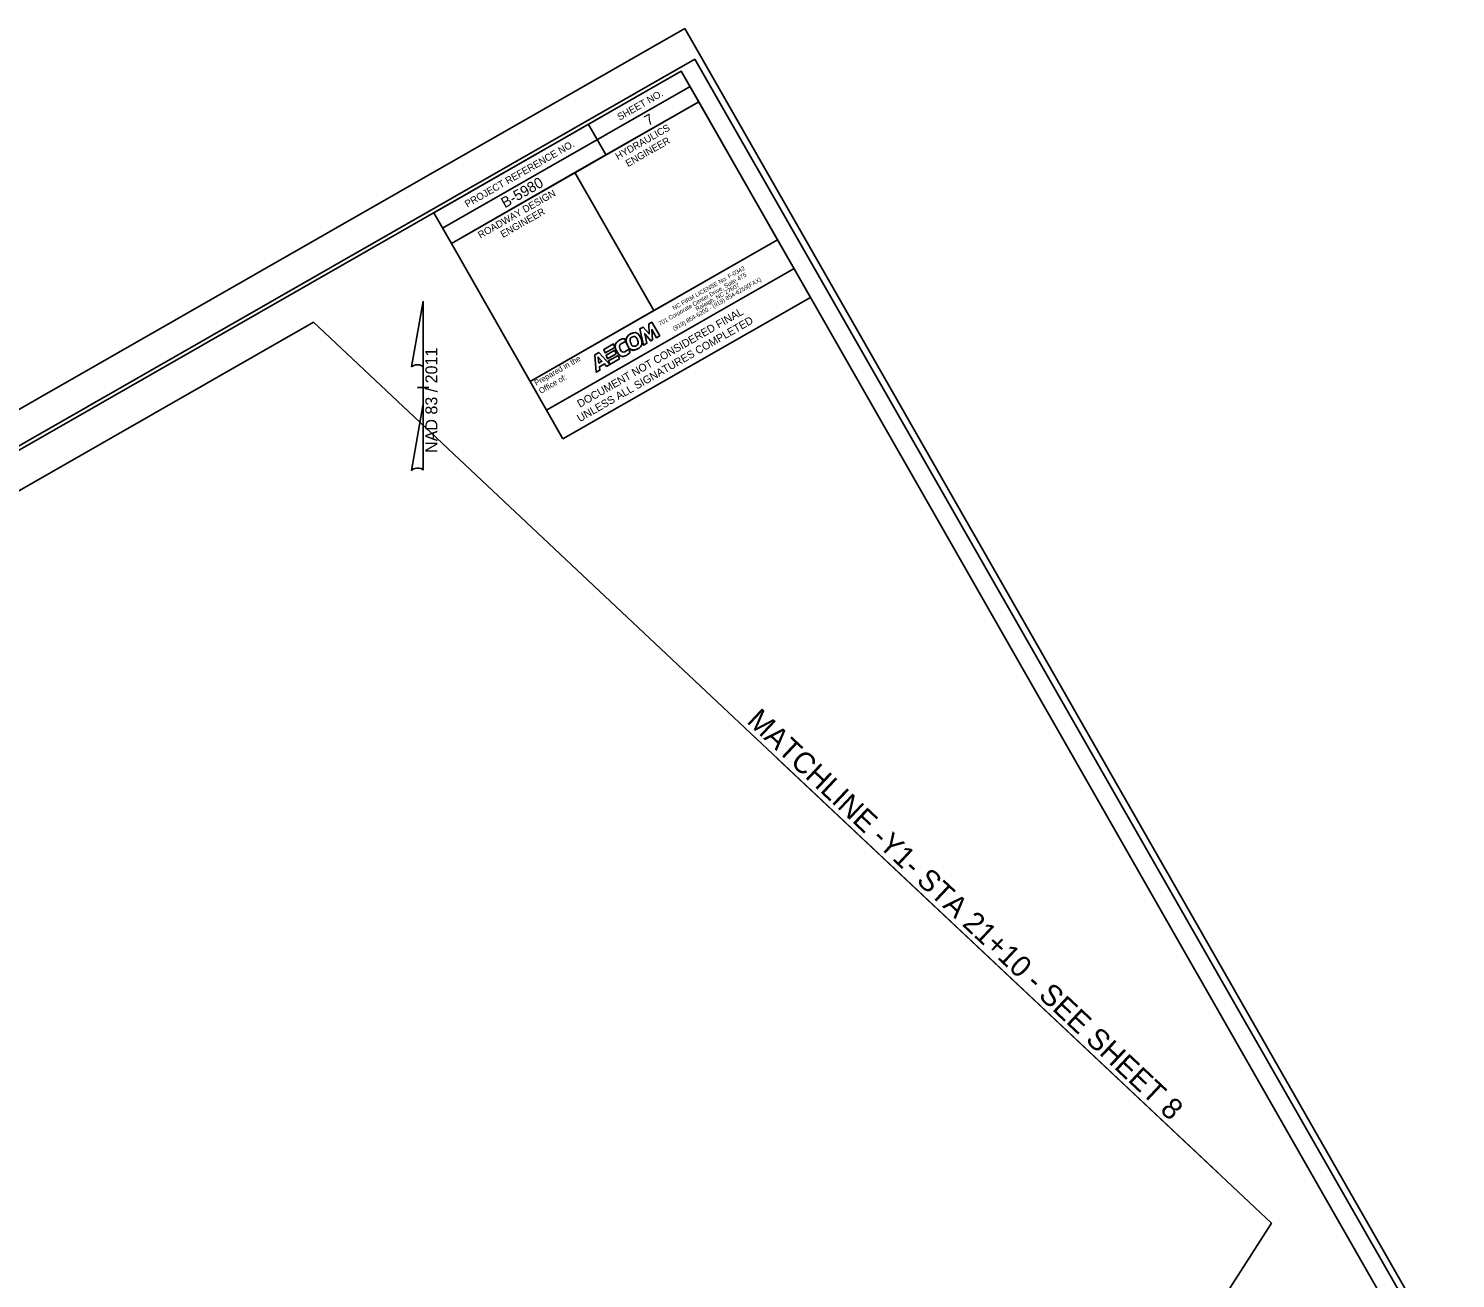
# Model space of a CAD drawing. Extents: x 2344815 to 2346837, y 841953 to 843752.
# Drawn here: x 2345826 to 2346837, y 842867 to 843752 of the extents above; entities that cross this region are included whole.
import ezdxf

# ---------------------------------------------------------------- set-up
doc = ezdxf.new("R2010")
doc.units = 0
for name, color, linetype in [('Default', 7, 'Continuous'), ('Matchline', 7, 'Continuous'), ('Matchline Text', 7, 'Continuous'), ('Old_Level_49', 7, 'Continuous'), ('Prop North Arrow NAD83 for Plan Sheets CELL', 7, 'Continuous'), ('Sheet Border Standard 30in CELL', 7, 'Continuous'), ('Sheet Clip Boundary CELL', 7, 'Continuous'), ('Sheet Data Field CELL', 7, 'Continuous'), ('Sheet Plot Border Inside CELL', 7, 'Continuous'), ('Sheet Plot Border Outside CELL', 7, 'Continuous'), ('Sheet Profile CELL', 7, 'Continuous'), ('Sheet Sticker Exception Certification CELL', 7, 'Continuous')]:
    doc.layers.add(name, color=color, linetype=linetype)

# ---------------------------------------------------------------- blocks, each defined once
blk = doc.blocks.new('block 2')
at = {"layer": 'Default'}
for p, q in [((0.10234, 0.09375), (0.10197, 0.09133)), ((0.10966, 0.09375), (0.10234, 0.09375)), ((0.10929, 0.09133), (0.10966, 0.09375)), ((0.10114, 0.08576), (0.10078, 0.08333)), ((0.10846, 0.08576), (0.10114, 0.08576)), ((0.10137, 0.08733), (0.10174, 0.08975)), ((0.10782, 0.08733), (0.10137, 0.08733)), ((0.10174, 0.08975), (0.10818, 0.08975)), ((0.10197, 0.09133), (0.10929, 0.09133)), ((0.10818, 0.08975), (0.10782, 0.08733)), ((0.1081, 0.08333), (0.10846, 0.08576)), ((0.10078, 0.08333), (0.1081, 0.08333))]:
    blk.add_line(p, q, dxfattribs=at)
for points in [[(0.10929, 0.09133), (0.10197, 0.09133), (0.10234, 0.09375), (0.10966, 0.09375), (0.10929, 0.09133)], [(0.10846, 0.08576), (0.10114, 0.08576), (0.10078, 0.08333), (0.1081, 0.08333), (0.10846, 0.08576)], [(0.10782, 0.08733), (0.10137, 0.08733), (0.10174, 0.08975), (0.10818, 0.08975), (0.10782, 0.08733)]]:
    blk.add_lwpolyline(points, dxfattribs=at)
blk = doc.blocks.new('block 3')
at = {"layer": 'Default'}
blk.add_open_spline([(0.12275, 0.09393), (0.12554, 0.09373), (0.12726, 0.09146), (0.12695, 0.08843), (0.12663, 0.08531), (0.12411, 0.08298), (0.12127, 0.08318), (0.11848, 0.08338), (0.11676, 0.08565), (0.11707, 0.08868), (0.11739, 0.0918), (0.11991, 0.09413), (0.12275, 0.09393)], degree=3, dxfattribs=at)

msp = doc.modelspace()

# ---------------------------------------------------------------- linework, layer by layer
at = {"layer": 'Default'}
for p, q in [((2346192.9, 843481.8), (2346368.2, 843582.1)), ((2346204.5, 843461.4), (2346379.9, 843561.7))]:
    msp.add_line(p, q, dxfattribs=at)
at = {"layer": 'Matchline'}
msp.add_lwpolyline([(2346668.8, 842941.4), (2346297.9, 843290.1)], dxfattribs=at)
at = {"layer": 'Old_Level_49'}
for p, q in [((2346261.2, 843540.6), (2346259, 843539.4)), ((2346259, 843539.4), (2346261.6, 843527.8)), ((2346265.5, 843535.8), (2346261.2, 843540.6)), ((2346267.4, 843544.2), (2346265.2, 843542.9)), ((2346265.2, 843542.9), (2346265.5, 843535.8)), ((2346273.2, 843534.5), (2346267.4, 843544.2)), ((2346267.9, 843531.5), (2346267.5, 843538.9)), ((2346267.5, 843538.9), (2346270.8, 843533.1)), ((2346261.6, 843527.8), (2346264, 843529.2)), ((2346264, 843529.2), (2346262.4, 843535.9)), ((2346262.4, 843535.9), (2346266.7, 843530.8)), ((2346266.7, 843530.8), (2346267.9, 843531.5)), ((2346270.8, 843533.1), (2346273.2, 843534.5)), ((2346229.8, 843522.7), (2346227.1, 843521.1)), ((2346227.1, 843521.1), (2346228.1, 843508.7)), ((2346229.9, 843515.1), (2346229.4, 843519.4)), ((2346229.4, 843519.4), (2346229.4, 843519.4)), ((2346229.4, 843519.4), (2346232.1, 843516.4)), ((2346237.6, 843514.1), (2346229.8, 843522.7)), ((2346228.1, 843508.7), (2346230.6, 843510.1)), ((2346232.1, 843516.4), (2346229.9, 843515.1)), ((2346230.3, 843512.5), (2346233.8, 843514.5)), ((2346230.6, 843510.1), (2346230.3, 843512.5)), ((2346233.8, 843514.5), (2346235.3, 843512.8)), ((2346235.3, 843512.8), (2346237.6, 843514.1))]:
    msp.add_line(p, q, dxfattribs=at)
for points in [[(2346273.2, 843534.5), (2346267.4, 843544.2), (2346265.2, 843542.9), (2346265.5, 843535.8), (2346261.2, 843540.6), (2346259, 843539.4), (2346261.6, 843527.8), (2346264, 843529.2), (2346262.4, 843535.9), (2346266.7, 843530.8), (2346267.9, 843531.5), (2346267.5, 843538.9), (2346270.8, 843533.1), (2346273.2, 843534.5)], [(2346235.3, 843512.8), (2346237.6, 843514.1), (2346229.8, 843522.7), (2346227.1, 843521.1), (2346228.1, 843508.7), (2346230.6, 843510.1), (2346230.3, 843512.5), (2346233.8, 843514.5), (2346235.3, 843512.8)], [(2346229.9, 843515.1), (2346229.4, 843519.4), (2346229.4, 843519.4), (2346232.1, 843516.4), (2346229.9, 843515.1)]]:
    msp.add_lwpolyline(points, dxfattribs=at)
for points in [[(2346252.6, 843536), (2346255.4, 843537.3), (2346258.2, 843536.1), (2346259.5, 843533), (2346260.9, 843529.9), (2346259.8, 843526.4), (2346257, 843525), (2346256.6, 843524.9), (2346256.3, 843524.7), (2346255.9, 843524.6)], [(2346251, 843525.1), (2346250.5, 843524.5), (2346249.6, 843523.8), (2346249.1, 843523.6), (2346247.6, 843522.7), (2346245.9, 843523.2), (2346245.1, 843524.8), (2346244.2, 843526.5), (2346244.8, 843528.4), (2346246.5, 843529.3), (2346247.3, 843529.8), (2346248.1, 843529.9), (2346249.1, 843529.8), (2346249.1, 843529.8), (2346248.2, 843532.4), (2346248.2, 843532.4), (2346246.9, 843532.4), (2346245.9, 843532.2), (2346244.9, 843531.6), (2346242.1, 843530), (2346241.1, 843526.3), (2346242.7, 843523.3), (2346244.3, 843520.3), (2346247.3, 843519.4), (2346250, 843521), (2346250.5, 843521.3), (2346251.5, 843521.9), (2346252, 843522.6), (2346252, 843522.6), (2346251, 843525.1), (2346251, 843525.1)], [(2346251, 843525.1), (2346250.5, 843524.5), (2346249.6, 843523.8), (2346249.1, 843523.6), (2346247.6, 843522.7), (2346245.9, 843523.2), (2346245.1, 843524.8), (2346244.2, 843526.5), (2346244.8, 843528.4), (2346246.5, 843529.3), (2346247.3, 843529.8), (2346248.1, 843529.9), (2346249.1, 843529.8), (2346249.1, 843529.8), (2346248.2, 843532.4), (2346248.2, 843532.4), (2346246.9, 843532.4), (2346245.9, 843532.2), (2346244.9, 843531.6), (2346242.1, 843530), (2346241.1, 843526.3), (2346242.7, 843523.3), (2346244.3, 843520.3), (2346247.3, 843519.4), (2346250, 843521), (2346250.5, 843521.3), (2346251.5, 843521.9), (2346252, 843522.6), (2346252, 843522.6), (2346251, 843525.1), (2346251, 843525.1)], [(2346255.9, 843524.6), (2346253.5, 843524.1), (2346251.3, 843525.3), (2346250.1, 843528), (2346248.7, 843531.1), (2346249.8, 843534.6), (2346252.6, 843536)], [(2346257.3, 843531.5), (2346256.7, 843533.3), (2346255.4, 843534.3), (2346254, 843533.8), (2346252.5, 843533.3), (2346251.8, 843531.5), (2346252.4, 843529.6), (2346253, 843527.7), (2346254.4, 843526.8), (2346255.8, 843527.2), (2346257.3, 843527.7), (2346258, 843529.5), (2346257.3, 843531.5)], [(2346257.3, 843531.5), (2346256.7, 843533.3), (2346255.4, 843534.3), (2346254, 843533.8), (2346252.5, 843533.3), (2346251.8, 843531.5), (2346252.4, 843529.6), (2346253, 843527.7), (2346254.4, 843526.8), (2346255.8, 843527.2), (2346257.3, 843527.7), (2346258, 843529.5), (2346257.3, 843531.5)]]:
    msp.add_open_spline(points, degree=3, dxfattribs=at)
at = {"layer": 'Prop North Arrow NAD83 for Plan Sheets CELL'}
for p, q in [((2346097.2, 843512.5), (2346105.4, 843558.9)), ((2346105.5, 843558.9), (2346105.5, 843511.1)), ((2346105.5, 843486.3), (2346105.5, 843512.5)), ((2346105.5, 843511.1), (2346105.5, 843512.4)), ((2346101.5, 843497.8), (2346101.4, 843497.8)), ((2346101.5, 843497.8), (2346109.5, 843497.9)), ((2346105, 843497.9), (2346101.5, 843497.8)), ((2346105.5, 843486.3), (2346097.1, 843439)), ((2346105.5, 843439.2), (2346105.5, 843486.3))]:
    msp.add_line(p, q, dxfattribs=at)
for centre, start_param, end_param in [((2346101.4, 843512), 0.211319, 2.90315), ((2346101.4, 843438.8), 0.19626, 3.136524)]:
    msp.add_ellipse(centre, major_axis=(4.23, 0.02), ratio=0.461128, start_param=start_param, end_param=end_param, dxfattribs=at)
at = {"layer": 'Sheet Border Standard 30in CELL'}
for p, q in [((2346119.2, 843610.7), (2346294.5, 843711)), ((2346125.4, 843599.9), (2346300.7, 843700.1)), ((2346125.4, 843599.9), (2346300.7, 843700.1)), ((2346222.5, 843684.2), (2346235, 843662.5)), ((2346213, 843650), (2346268.9, 843552.4))]:
    msp.add_line(p, q, dxfattribs=at)
for points in [[(2346288.2, 843721.9), (2344973.7, 842970.1), (2345494.9, 842058.6), (2346809.5, 842810.4)], [(2346112.9, 843621.6), (2346288.2, 843721.9), (2346300.7, 843700.1), (2346125.4, 843599.9)], [(2346213, 843650), (2346300.7, 843700.1), (2346356.5, 843602.5), (2346268.9, 843552.3)], [(2346125.4, 843599.9), (2346213, 843650), (2346268.9, 843552.3), (2346181.2, 843502.2)]]:
    msp.add_lwpolyline(points, close=True, dxfattribs=at)
at = {"layer": 'Sheet Clip Boundary CELL'}
msp.add_line((2346647.5, 842961.5), (2346356, 843235.4), dxfattribs=at)
msp.add_lwpolyline([(2345008, 842960.9), (2345464.5, 842162.6), (2345542.9, 842193.6), (2345576.3, 842133.9), (2345624.5, 842161.5), (2346579, 842707.3), (2346706.4, 842906.1), (2346706.4, 842906.1), (2346706.4, 842906.1), (2346027.7, 843544), (2346027.7, 843544), (2346027.7, 843544), (2346023.3, 843541.5)], close=True, dxfattribs=at)
at = {"layer": 'Sheet Plot Border Inside CELL'}
msp.add_lwpolyline([(2346297.9, 843730.3), (2344837.5, 842895.1), (2345361.2, 841979.2), (2346821.7, 842814.4)], close=True, dxfattribs=at)
at = {"layer": 'Sheet Plot Border Outside CELL'}
msp.add_lwpolyline([(2346290.7, 843752.1), (2344815, 842908.1), (2345361, 841953.2), (2346836.8, 842797.2)], close=True, dxfattribs=at)
at = {"layer": 'Sheet Profile CELL'}
msp.add_line((2346181.2, 843502.2), (2346192.9, 843481.8), dxfattribs=at)
at = {"layer": 'Sheet Sticker Exception Certification CELL'}
for p, q in [((2346181.2, 843502.2), (2346356.5, 843602.5)), ((2346356.5, 843602.4), (2346368.2, 843582)), ((2346368.2, 843582.1), (2346192.9, 843481.8)), ((2346192.9, 843481.8), (2346368.2, 843582.1)), ((2346368.2, 843582), (2346379.9, 843561.6)), ((2346379.9, 843561.7), (2346204.5, 843461.4)), ((2346192.9, 843481.8), (2346181.2, 843502.2)), ((2346204.5, 843461.4), (2346192.9, 843481.8))]:
    msp.add_line(p, q, dxfattribs=at)

# ---------------------------------------------------------------- block references
at = {"layer": 'Old_Level_49', "xscale": 1084.8432715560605, "yscale": 1084.8432715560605, "rotation": 29.760945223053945}
for name in ['block 3', 'block 2']:
    msp.add_blockref(name, (2346187.6, 843381.4), dxfattribs=at)

# ---------------------------------------------------------------- texts
at = {"layer": 'Matchline Text'}
msp.add_text('MATCHLINE -Y1- STA 21+10 - SEE SHEET 8', height=15, rotation=316.7751, dxfattribs=at).set_placement((2346334, 843260.8))
at = {"layer": 'Old_Level_49'}
for s, height, p in [('701 Corporate Center Drive, Suite 475', 3.013, (2346273.2, 843541.5)), ('NC FIRM LICENSE No: F-0342', 3.013, (2346283.1, 843552.5)), ('(919) 854-6200 - (919) 854-6259(FAX)', 3.013, (2346283.3, 843538)), ('Raleigh, NC 27607', 3.013, (2346299.5, 843551.9)), ('Prepared in the ', 4.018, (2346185.6, 843499)), ('Office of:', 4.02, (2346188.8, 843493.3))]:
    msp.add_text(s, height=height, rotation=29.7609, dxfattribs=at).set_placement(p)
at = {"layer": 'Prop North Arrow NAD83 for Plan Sheets CELL'}
msp.add_text('NAD 83 / 2011', height=8.501, rotation=90, dxfattribs=at).set_placement((2346115.5, 843451.5))
at = {"layer": 'Sheet Border Standard 30in CELL'}
for s, p in [('SHEET NO.', (2346244.7, 843686.8)), ('HYDRAULICS', (2346243.4, 843658.9)), ('PROJECT REFERENCE NO.', (2346136.7, 843625.2)), ('ENGINEER', (2346250.6, 843653.9)), ('ROADWAY DESIGN', (2346146, 843603.2)), ('ENGINEER', (2346162, 843603.7))]:
    msp.add_text(s, height=5, rotation=29.7645, dxfattribs=at).set_placement(p)
at = {"layer": 'Sheet Data Field CELL'}
for s, p in [('7', (2346264.9, 843682.9)), ('B-5980', (2346163.3, 843624.7))]:
    msp.add_text(s, height=7.5, rotation=29.7645, dxfattribs=at).set_placement(p)
at = {"layer": 'Sheet Sticker Exception Certification CELL'}
for s, p in [('UNLESS ALL SIGNATURES COMPLETED', (2346216.4, 843473.2)), ('DOCUMENT NOT CONSIDERED FINAL', (2346216.5, 843483.4))]:
    msp.add_text(s, height=5.5, rotation=29.7645, dxfattribs=at).set_placement(p)

doc.saveas('drawing.dxf')
